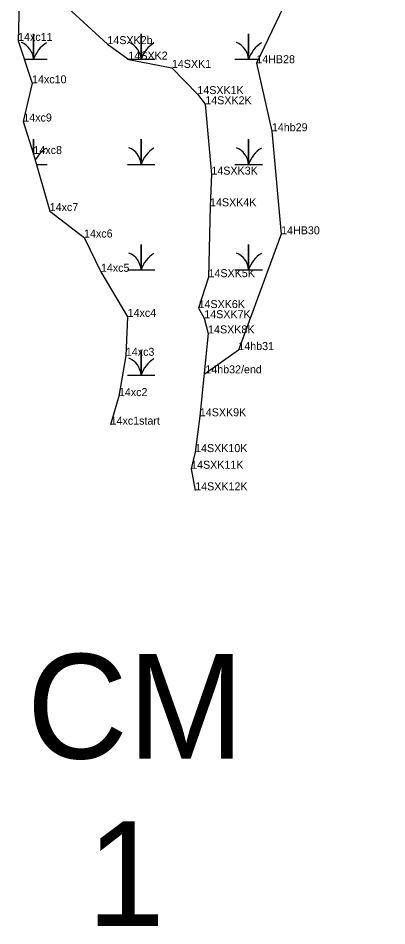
# Model space of a CAD drawing. Extents: x 2072529 to 2268796, y 436423 to 470397.
# Drawn here: x 2253780 to 2254011, y 442555 to 443122 of the extents above; entities that cross this region are included whole.
import ezdxf

# ---------------------------------------------------------------- set-up
doc = ezdxf.new("R2010")
doc.units = 0
for name, color, linetype in [('Default', 7, 'Continuous'), ('Exist Environmental Wetland Boundary', 7, 'Continuous'), ('Exist Environmental Wetland Boundary Cogo Comment', 7, 'Continuous'), ('Exist Environmental Wetland Boundary Cogo Point CELL', 7, 'Continuous'), ('Exist Hydro Jurisdictional Stream or Body of Water NEU Mitigable', 7, 'Continuous'), ('Exist Hydro Jurisdictional Stream or Body of Water NEU Mitigable Cogo Comment', 7, 'Continuous'), ('Exist Hydro Swamp or Marsh', 7, 'Continuous')]:
    doc.layers.add(name, color=color, linetype=linetype)

msp = doc.modelspace()

# ---------------------------------------------------------------- linework, layer by layer
at = {"layer": 'Exist Environmental Wetland Boundary'}
for points in [[(2254016.44, 443436.8), (2253980.84, 443407.93), (2253969.11, 443329.26), (2253933.2, 443297.83), (2253950.65, 443241.78), (2253964.42, 443201.58), (2253960.36, 443159.47), (2253928.92, 443094), (2253938.65, 443051.47), (2253944.44, 442987.07), (2253917.67, 442914.74), (2253896.2, 442899.57)], [(2253780.68, 443131.44), (2253779.94, 443107.95), (2253788.65, 443081.45), (2253783.18, 443057.57), (2253789.53, 443037.25), (2253799.69, 443001.59), (2253821.17, 442985.07), (2253831.72, 442963.63), (2253848.44, 442935.49), (2253847.31, 442911.16), (2253842.97, 442885.97), (2253837.77, 442868.1)]]:
    msp.add_lwpolyline(points, dxfattribs=at)
at = {"layer": 'Exist Environmental Wetland Boundary Cogo Point CELL'}
for p, q in [((2253779.94, 443107.95), (2253779.94, 443107.95)), ((2253835.76, 443105.92), (2253835.76, 443105.92)), ((2253849.13, 443096.34), (2253849.13, 443096.34)), ((2253928.92, 443094), (2253928.92, 443094)), ((2253876.1, 443091.1), (2253876.1, 443091.1)), ((2253788.65, 443081.45), (2253788.65, 443081.45)), ((2253892.03, 443074.69), (2253892.03, 443074.69)), ((2253897, 443068.35), (2253897, 443068.35)), ((2253783.18, 443057.57), (2253783.18, 443057.57)), ((2253938.65, 443051.47), (2253938.65, 443051.47)), ((2253789.53, 443037.25), (2253789.53, 443037.25)), ((2253900.82, 443024.39), (2253900.82, 443024.39)), ((2253899.97, 443004.58), (2253899.97, 443004.58)), ((2253799.69, 443001.59), (2253799.69, 443001.59)), ((2253944.44, 442987.07), (2253944.44, 442987.07)), ((2253821.17, 442985.07), (2253821.17, 442985.07)), ((2253831.72, 442963.63), (2253831.72, 442963.63)), ((2253899.02, 442960.29), (2253899.02, 442960.29)), ((2253892.78, 442940.98), (2253892.78, 442940.98)), ((2253848.44, 442935.49), (2253848.44, 442935.49)), ((2253896.37, 442934.65), (2253896.37, 442934.65)), ((2253898.76, 442925.15), (2253898.76, 442925.15)), ((2253917.67, 442914.74), (2253917.67, 442914.74)), ((2253847.31, 442911.16), (2253847.31, 442911.16)), ((2253897.03, 442900.16), (2253897.03, 442900.16)), ((2253842.97, 442885.97), (2253842.97, 442885.97)), ((2253893.58, 442873.35), (2253893.58, 442873.35)), ((2253837.77, 442868.1), (2253837.77, 442868.1)), ((2253890.62, 442850.98), (2253890.62, 442850.98)), ((2253888.14, 442840.57), (2253888.14, 442840.57)), ((2253890.71, 442827.06), (2253890.71, 442827.06))]:
    msp.add_line(p, q, dxfattribs=at)
at = {"layer": 'Exist Hydro Jurisdictional Stream or Body of Water NEU Mitigable'}
msp.add_lwpolyline([(2253806.17, 443133.02), (2253835.76, 443105.92), (2253849.13, 443096.34), (2253876.1, 443091.1), (2253892.03, 443074.69), (2253897, 443068.35), (2253900.82, 443024.39), (2253899.97, 443004.58), (2253899.02, 442960.29), (2253892.78, 442940.98), (2253896.37, 442934.65), (2253898.76, 442925.15), (2253893.58, 442873.35), (2253890.62, 442850.98), (2253888.14, 442840.57), (2253890.71, 442827.06)], dxfattribs=at)
at = {"layer": 'Exist Hydro Swamp or Marsh'}
for points in [[(2253783.7, 443096.52), (2253789.59, 443096.52), (2253789.59, 443112.3), (2253789.59, 443096.52), (2253798.19, 443096.52)], [(2253848.24, 443096.52), (2253856.84, 443096.52), (2253856.84, 443112.3), (2253856.84, 443096.52), (2253865.44, 443096.52)], [(2253915.49, 443096.52), (2253924.09, 443096.52), (2253924.09, 443112.3), (2253924.09, 443096.52), (2253930.13, 443096.52)], [(2253789.59, 443037.04), (2253789.59, 443046.5), (2253789.59, 443037.04)], [(2253848.24, 443030.72), (2253856.84, 443030.72), (2253856.84, 443046.5), (2253856.84, 443030.72), (2253865.44, 443030.72)], [(2253915.49, 443030.72), (2253924.09, 443030.72), (2253924.09, 443046.5), (2253924.09, 443030.72), (2253932.69, 443030.72)], [(2253791.39, 443030.72), (2253798.19, 443030.72)], [(2253848.24, 442964.92), (2253856.84, 442964.92), (2253856.84, 442980.7), (2253856.84, 442964.92), (2253865.44, 442964.92)], [(2253915.49, 442964.92), (2253924.09, 442964.92), (2253924.09, 442980.7), (2253924.09, 442964.92), (2253932.69, 442964.92)], [(2253848.24, 442899.12), (2253856.84, 442899.12), (2253856.84, 442914.9), (2253856.84, 442899.12), (2253865.44, 442899.12)]]:
    msp.add_lwpolyline(points, dxfattribs=at)
for centre, radius, start, end in [((2253777.32, 443095.63), 12.3, 4.1403, 67.535), ((2253807.83, 443090.46), 19.22, 122.1274, 161.6222), ((2253844.57, 443095.63), 12.3, 4.1403, 67.535), ((2253875.08, 443090.46), 19.22, 122.1274, 161.6222), ((2253911.82, 443095.63), 12.3, 4.1403, 67.535), ((2253942.33, 443090.46), 19.22, 122.1274, 161.6222), ((2253807.83, 443024.66), 19.22, 122.1274, 153.3155), ((2253844.57, 443029.83), 12.3, 4.1403, 67.535), ((2253875.08, 443024.66), 19.22, 122.1274, 161.6222), ((2253911.82, 443029.83), 12.3, 4.1403, 67.535), ((2253942.33, 443024.66), 19.22, 122.1274, 161.6222), ((2253844.57, 442964.03), 12.3, 4.1403, 67.535), ((2253875.08, 442958.86), 19.22, 122.1274, 161.6222), ((2253911.82, 442964.03), 12.3, 4.1403, 67.535), ((2253942.33, 442958.86), 19.22, 122.1274, 161.6222), ((2253844.57, 442898.23), 12.3, 4.1403, 67.535), ((2253875.08, 442893.06), 19.22, 122.1274, 161.6222)]:
    msp.add_arc(centre, radius, start, end, dxfattribs=at)

# ---------------------------------------------------------------- texts
at = {"layer": 'Default'}
for s, p in [('CM', (2253785.38, 442659.45)), ('CM', (2253785.38, 442659.45)), ('CM', (2253785.38, 442659.45)), ('1', (2253823.03, 442554.91)), ('1', (2253823.03, 442554.91)), ('1', (2253823.03, 442554.91))]:
    msp.add_text(s, height=65.34, dxfattribs=at).set_placement(p)
at = {"layer": 'Exist Environmental Wetland Boundary Cogo Comment'}
for s, p in [('14xc11', (2253779.94, 443107.95)), ('14xc10', (2253788.65, 443081.45)), ('14xc9', (2253783.18, 443057.57)), ('14hb29', (2253938.65, 443051.47)), ('14xc8', (2253789.53, 443037.25)), ('14xc7', (2253799.69, 443001.59)), ('14HB30', (2253944.44, 442987.07)), ('14xc6', (2253821.17, 442985.07)), ('14xc5', (2253831.72, 442963.63)), ('14xc4', (2253848.44, 442935.49)), ('14hb31', (2253917.67, 442914.74)), ('14xc3', (2253847.31, 442911.16)), ('14hb32/end', (2253897.02, 442900.17)), ('14xc2', (2253842.97, 442885.97)), ('14xc1start', (2253837.77, 442868.1))]:
    msp.add_text(s, height=5, dxfattribs=at).set_placement(p)
at = {"layer": 'Exist Hydro Jurisdictional Stream or Body of Water NEU Mitigable Cogo Comment'}
for s, p in [('14SXK2b', (2253835.76, 443105.92)), ('14SXK2', (2253848.93, 443096.29)), ('14SXK1', (2253876.1, 443091.1)), ('14HB28', (2253928.92, 443094)), ('14SXK1K', (2253892.03, 443074.69)), ('14SXK2K', (2253897, 443068.35)), ('14SXK3K', (2253900.82, 443024.39)), ('14SXK4K', (2253899.97, 443004.58)), ('14SXK5K', (2253899.02, 442960.29)), ('14SXK6K', (2253892.78, 442940.98)), ('14SXK7K', (2253896.37, 442934.65)), ('14SXK8K', (2253898.76, 442925.15)), ('14SXK9K', (2253893.58, 442873.35)), ('14SXK10K', (2253890.62, 442850.98)), ('14SXK11K', (2253888.14, 442840.57)), ('14SXK12K', (2253890.71, 442827.06))]:
    msp.add_text(s, height=5, dxfattribs=at).set_placement(p)

doc.saveas('drawing.dxf')
